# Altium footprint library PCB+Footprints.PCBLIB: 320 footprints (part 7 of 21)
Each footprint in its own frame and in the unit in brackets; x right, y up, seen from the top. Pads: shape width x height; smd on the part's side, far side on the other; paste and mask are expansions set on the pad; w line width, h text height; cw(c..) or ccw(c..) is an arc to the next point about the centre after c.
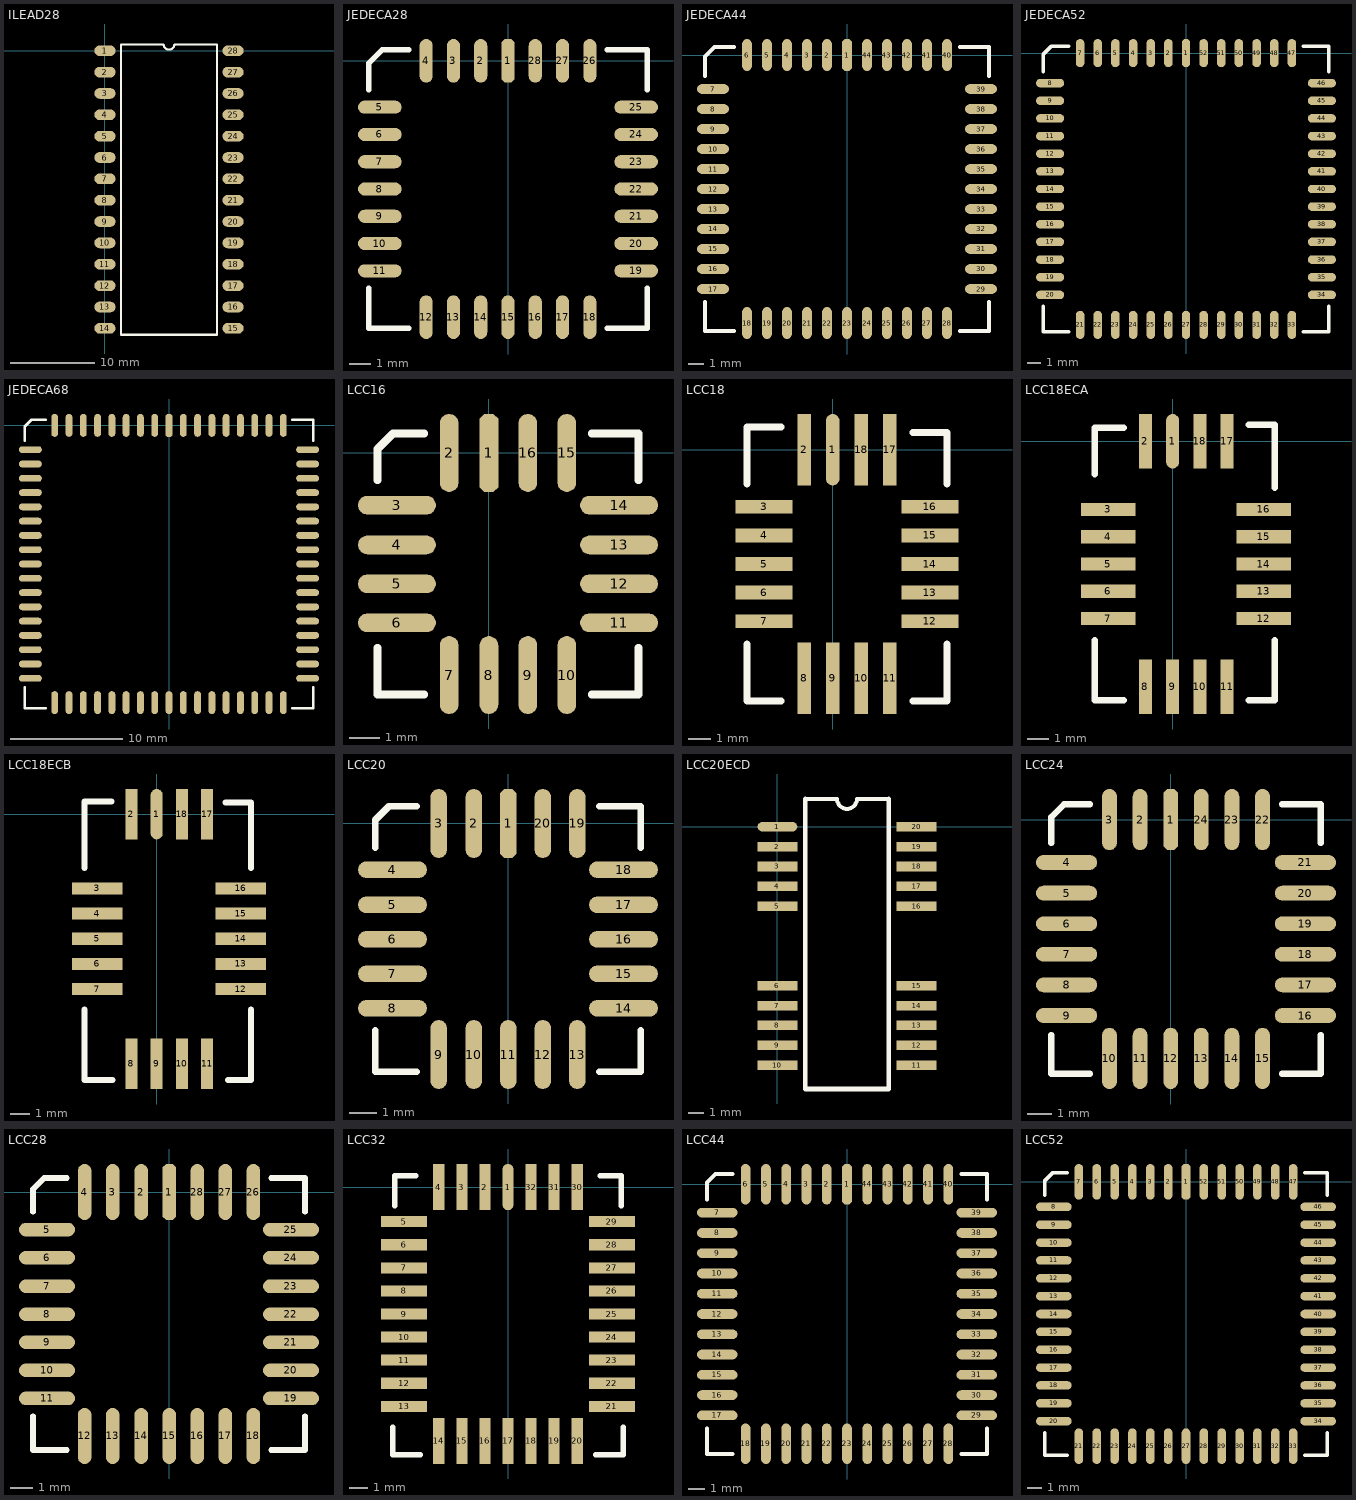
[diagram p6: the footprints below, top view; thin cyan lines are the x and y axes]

## ILEAD28 [mil]
pads (28):
  oval 100x50 smd: 1(0,0) 2(0,-100) 3(0,-200) 4(0,-300) 5(0,-400) 6(0,-500) 7(0,-600) 8(0,-700) 9(0,-800) 10(0,-900) 11(0,-1000) 12(0,-1100) 13(0,-1200) 14(0,-1300) 15(600,-1300) 16(600,-1200) 17(600,-1100) 18(600,-1000) 19(600,-900) 20(600,-800) 21(600,-700) 22(600,-600) 23(600,-500) 24(600,-400) 25(600,-300) 26(600,-200) 27(600,-100) 28(600,0)
TopOverlay:
  lines w10: 75,-1330 75,30 275,30 ccw(c300,30) 325,30 525,30 525,-1330 75,-1330

## JEDECA28 [mil]
pads (28):
  oct 24x80 smd: 1(0,0)
  oval 24x80 smd: 2(-50,0) 3(-100,0) 4(-150,0) 12(-150,-470) 13(-100,-470) 14(-50,-470) 15(0,-470) 16(50,-470) 17(100,-470) 18(150,-470) 26(150,0) 27(100,0) 28(50,0)
  oval 80x24 smd: 5(-235,-85) 6(-235,-135) 7(-235,-185) 8(-235,-235) 9(-235,-285) 10(-235,-335) 11(-235,-385) 19(235,-385) 20(235,-335) 21(235,-285) 22(235,-235) 23(235,-185) 24(235,-135) 25(235,-85)
TopOverlay:
  lines w10: -255,-417 -255,-490 -182,-490 ; -255,-53 -255,-4 -231,20 -182,20 ; 182,-490 255,-490 255,-417 ; 182,20 255,20 255,-53

## JEDECA44 [mil]
pads (44):
  oct 24x80 smd: 1(0,0)
  oval 24x80 smd: 2(-50,0) 3(-100,0) 4(-150,0) 5(-200,0) 6(-250,0) 18(-250,-670) 19(-200,-670) 20(-150,-670) 21(-100,-670) 22(-50,-670) 23(0,-670) 24(50,-670) 25(100,-670) 26(150,-670) 27(200,-670) 28(250,-670) 40(250,0) 41(200,0) 42(150,0) 43(100,0) 44(50,0)
  oval 80x24 smd: 7(-335,-85) 8(-335,-135) 9(-335,-185) 10(-335,-235) 11(-335,-285) 12(-335,-335) 13(-335,-385) 14(-335,-435) 15(-335,-485) 16(-335,-535) 17(-335,-585) 29(335,-585) 30(335,-535) 31(335,-485) 32(335,-435) 33(335,-385) 34(335,-335) 35(335,-285) 36(335,-235) 37(335,-185) 38(335,-135) 39(335,-85)
TopOverlay:
  lines w10: -355,-617 -355,-690 -282,-690 ; -355,-53 -355,-4 -331,20 -282,20 ; 282,-690 355,-690 355,-617 ; 282,20 355,20 355,-53

## JEDECA52 [mil]
pads (52):
  oct 24x80 smd: 1(0,0)
  oval 24x80 smd: 2(-50,0) 3(-100,0) 4(-150,0) 5(-200,0) 6(-250,0) 7(-300,0) 21(-300,-770) 22(-250,-770) 23(-200,-770) 24(-150,-770) 25(-100,-770) 26(-50,-770) 27(0,-770) 28(50,-770) 29(100,-770) 30(150,-770) 31(200,-770) 32(250,-770) 33(300,-770) 47(300,0) 48(250,0) 49(200,0) 50(150,0) 51(100,0) 52(50,0)
  oval 80x24 smd: 8(-385,-85) 9(-385,-135) 10(-385,-185) 11(-385,-235) 12(-385,-285) 13(-385,-335) 14(-385,-385) 15(-385,-435) 16(-385,-485) 17(-385,-535) 18(-385,-585) 19(-385,-635) 20(-385,-685) 34(385,-685) 35(385,-635) 36(385,-585) 37(385,-535) 38(385,-485) 39(385,-435) 40(385,-385) 41(385,-335) 42(385,-285) 43(385,-235) 44(385,-185) 45(385,-135) 46(385,-85)
TopOverlay:
  lines w10: -405,-717 -405,-790 -332,-790 ; -405,-53 -405,-4 -381,20 -332,20 ; 332,-790 405,-790 405,-717 ; 332,20 405,20 405,-53

## JEDECA68 [mil]
pads (68):
  oct 24x80 smd: 1(0,0)
  oval 24x80 smd: 2(-50,0) 3(-100,0) 4(-150,0) 5(-200,0) 6(-250,0) 7(-300,0) 8(-350,0) 9(-400,0) 27(-400,-970) 28(-350,-970) 29(-300,-970) 30(-250,-970) 31(-200,-970) 32(-150,-970) 33(-100,-970) 34(-50,-970) 35(0,-970) 36(50,-970) 37(100,-970) 38(150,-970) 39(200,-970) 40(250,-970) 41(300,-970) 42(350,-970) 43(400,-970) 61(400,0) 62(350,0) 63(300,0) 64(250,0) 65(200,0) 66(150,0) 67(100,0) 68(50,0)
  oval 80x24 smd: 10(-485,-85) 11(-485,-135) 12(-485,-185) 13(-485,-235) 14(-485,-285) 15(-485,-335) 16(-485,-385) 17(-485,-435) 18(-485,-485) 19(-485,-535) 20(-485,-585) 21(-485,-635) 22(-485,-685) 23(-485,-735) 24(-485,-785) 25(-485,-835) 26(-485,-885) 44(485,-885) 45(485,-835) 46(485,-785) 47(485,-735) 48(485,-685) 49(485,-635) 50(485,-585) 51(485,-535) 52(485,-485) 53(485,-435) 54(485,-385) 55(485,-335) 56(485,-285) 57(485,-235) 58(485,-185) 59(485,-135) 60(485,-85)
TopOverlay:
  lines w10: -505,-917 -505,-990 -432,-990 ; -505,-53 -505,-4 -481,20 -432,20 ; 432,-990 505,-990 505,-917 ; 432,20 505,20 505,-53

## LCC16 [mil]
pads (16):
  oct 24x100 smd: 1(0,0)
  oval 24x100 smd: 2(-51,0) 7(-51,-285) 8(0,-285) 9(50,-285) 10(100,-285) 15(100,0) 16(50,0)
  oval 100x24 smd: 3(-118,-67) 4(-118,-118) 5(-118,-168) 6(-118,-218) 11(167,-218) 12(167,-168) 13(167,-118) 14(167,-67)
TopOverlay:
  lines w10: -143,-250 -143,-310 -83,-310 ; -143,-35 -143,5 -123,25 -83,25 ; 132,-310 192,-310 192,-250 ; 132,25 192,25 192,-35

## LCC18 [mil]
pads (18):
  oval 24x125 smd: 1(0,0)
  rect 24x125 smd: 2(-50,0) 8(-50,-400) 9(0,-400) 10(50,-400) 11(100,-400) 17(100,0) 18(50,0)
  rect 100x24 smd: 3(-120,-100) 4(-120,-150) 5(-120,-200) 6(-120,-250) 7(-120,-300) 12(170,-300) 13(170,-250) 14(170,-200) 15(170,-150) 16(170,-100)
TopOverlay:
  lines w12: -150,-340 -150,-440 -90,-440 ; -150,-60 -150,40 -90,40 ; 140,-440 200,-440 200,-340 ; 140,30 200,30 200,-60

## LCC18ECA [mil]
pads (18):
  oval 24x100 smd: 1(0,0)
  rect 24x100 smd: 2(-50,0) 8(-50,-450) 9(0,-450) 10(50,-450) 11(100,-450) 17(100,0) 18(50,0)
  rect 100x24 smd: 3(-118,-125) 4(-118,-175) 5(-118,-225) 6(-118,-275) 7(-118,-325) 12(167,-325) 13(167,-275) 14(167,-225) 15(167,-175) 16(167,-125)
TopOverlay:
  lines w12: -143,-365 -143,-475 -90,-475 ; -143,-60 -143,25 -90,25 ; 140,-475 187,-475 187,-365 ; 140,30 187,30 187,-85

## LCC18ECB [mil]
pads (18):
  oval 24x100 smd: 1(0,0)
  rect 24x100 smd: 2(-50,0) 8(-50,-495) 9(0,-495) 10(50,-495) 11(100,-495) 17(100,0) 18(50,0)
  rect 100x24 smd: 3(-118,-147) 4(-118,-197) 5(-118,-247) 6(-118,-297) 7(-118,-347) 12(167,-347) 13(167,-297) 14(167,-247) 15(167,-197) 16(167,-147)
TopOverlay:
  lines w12: -143,-387 -143,-527 -88,-527 ; -143,-107 -143,25 -90,25 ; 137,23 187,23 187,-107 ; 142,-527 187,-527 187,-387

## LCC20 [mil]
pads (20):
  oct 24x100 smd: 1(0,0)
  oval 24x100 smd: 2(-50,0) 3(-101,0) 9(-101,-335) 10(-50,-335) 11(0,-335) 12(50,-335) 13(100,-335) 19(100,0) 20(50,0)
  oval 100x24 smd: 4(-168,-67) 5(-168,-118) 6(-168,-168) 7(-168,-218) 8(-168,-268) 14(167,-268) 15(167,-218) 16(167,-168) 17(167,-118) 18(167,-67)
TopOverlay:
  lines w10: -193,-300 -193,-360 -133,-360 ; -193,-35 -193,5 -173,25 -133,25 ; 132,-360 192,-360 192,-300 ; 132,25 192,25 192,-35

## LCC20ECD [mil]
pads (20):
  oval 100x24 smd: 1(0,0)
  rect 100x24 smd: 2(0,-50) 3(0,-100) 4(0,-150) 5(0,-200) 6(0,-400) 7(0,-450) 8(0,-500) 9(0,-550) 10(0,-600) 11(350,-600) 12(350,-550) 13(350,-500) 14(350,-450) 15(350,-400) 16(350,-200) 17(350,-150) 18(350,-100) 19(350,-50) 20(350,0)
TopOverlay:
  lines w10: 70,70 150,70 ccw(c175,70) 200,70 280,70
  lines w12: 70,70 70,-660 280,-660 280,70

## LCC24 [mil]
pads (24):
  oct 24x100 smd: 1(0,0)
  oval 24x100 smd: 2(-50,0) 3(-100,0) 10(-100,-390) 11(-50,-390) 12(0,-390) 13(50,-390) 14(100,-390) 15(150,-390) 22(150,0) 23(100,0) 24(50,0)
  oval 100x24 smd: 4(-170,-70) 5(-170,-120) 6(-170,-170) 7(-170,-220) 8(-170,-270) 9(-170,-320) 16(220,-320) 17(220,-270) 18(220,-220) 19(220,-170) 20(220,-120) 21(220,-70)
TopOverlay:
  lines w10: -195,-352 -195,-415 -132,-415 ; -195,-38 -195,4 -174,25 -132,25 ; 182,-415 245,-415 245,-352 ; 182,25 245,25 245,-38

## LCC28 [mil]
pads (28):
  oct 24x100 smd: 1(0,0)
  oval 24x100 smd: 2(-50,0) 3(-101,0) 4(-151,0) 12(-151,-435) 13(-101,-435) 14(-50,-435) 15(0,-435) 16(50,-435) 17(100,-435) 18(150,-435) 26(150,0) 27(100,0) 28(50,0)
  oval 100x24 smd: 5(-218,-67) 6(-218,-117) 7(-218,-168) 8(-218,-218) 9(-218,-268) 10(-218,-318) 11(-218,-368) 19(217,-368) 20(217,-318) 21(217,-268) 22(217,-218) 23(217,-168) 24(217,-117) 25(217,-67)
TopOverlay:
  lines w10: -243,-400 -243,-460 -183,-460 ; -243,-35 -243,5 -223,25 -183,25 ; 182,-460 242,-460 242,-400 ; 182,25 242,25 242,-35

## LCC32 [mil]
pads (32):
  oval 24x100 smd: 1(0,0)
  rect 24x100 smd: 2(-50,0) 3(-100,0) 4(-150,0) 14(-150,-550) 15(-100,-550) 16(-50,-550) 17(0,-550) 18(50,-550) 19(100,-550) 20(150,-550) 30(150,0) 31(100,0) 32(50,0)
  rect 100x24 smd: 5(-225,-75) 6(-225,-125) 7(-225,-175) 8(-225,-225) 9(-225,-275) 10(-225,-325) 11(-225,-375) 12(-225,-425) 13(-225,-475) 21(225,-475) 22(225,-425) 23(225,-375) 24(225,-325) 25(225,-275) 26(225,-225) 27(225,-175) 28(225,-125) 29(225,-75)
TopOverlay:
  lines w12: -250,-520 -250,-580 -190,-580 ; -245,-40 -245,25 -200,25 ; 190,-580 250,-580 250,-520 ; 200,25 245,25 245,-40

## LCC44 [mil]
pads (44):
  oct 24x100 smd: 1(0,0)
  oval 24x100 smd: 2(-50,0) 3(-100,0) 4(-150,0) 5(-200,0) 6(-250,0) 18(-250,-640) 19(-200,-640) 20(-150,-640) 21(-100,-640) 22(-50,-640) 23(0,-640) 24(50,-640) 25(100,-640) 26(150,-640) 27(200,-640) 28(250,-640) 40(250,0) 41(200,0) 42(150,0) 43(100,0) 44(50,0)
  oval 100x24 smd: 7(-320,-70) 8(-320,-120) 9(-320,-170) 10(-320,-220) 11(-320,-270) 12(-320,-320) 13(-320,-370) 14(-320,-420) 15(-320,-470) 16(-320,-520) 17(-320,-570) 29(320,-570) 30(320,-520) 31(320,-470) 32(320,-420) 33(320,-370) 34(320,-320) 35(320,-270) 36(320,-220) 37(320,-170) 38(320,-120) 39(320,-70)
TopOverlay:
  lines w10: -345,-602 -345,-665 -282,-665 ; -345,-38 -345,4 -324,25 -282,25 ; 282,-665 345,-665 345,-602 ; 282,25 345,25 345,-38

## LCC52 [mil]
pads (52):
  oct 24x100 smd: 1(0,0)
  oval 24x100 smd: 2(-50,0) 3(-100,0) 4(-150,0) 5(-200,0) 6(-250,0) 7(-300,0) 21(-300,-740) 22(-250,-740) 23(-200,-740) 24(-150,-740) 25(-100,-740) 26(-50,-740) 27(0,-740) 28(50,-740) 29(100,-740) 30(150,-740) 31(200,-740) 32(250,-740) 33(300,-740) 47(300,0) 48(250,0) 49(200,0) 50(150,0) 51(100,0) 52(50,0)
  oval 100x24 smd: 8(-370,-70) 9(-370,-120) 10(-370,-170) 11(-370,-220) 12(-370,-270) 13(-370,-320) 14(-370,-370) 15(-370,-420) 16(-370,-470) 17(-370,-520) 18(-370,-570) 19(-370,-620) 20(-370,-670) 34(370,-670) 35(370,-620) 36(370,-570) 37(370,-520) 38(370,-470) 39(370,-420) 40(370,-370) 41(370,-320) 42(370,-270) 43(370,-220) 44(370,-170) 45(370,-120) 46(370,-70)
TopOverlay:
  lines w10: -395,-702 -395,-765 -332,-765 ; -395,-38 -395,4 -374,25 -332,25 ; 332,-765 395,-765 395,-702 ; 332,25 395,25 395,-38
